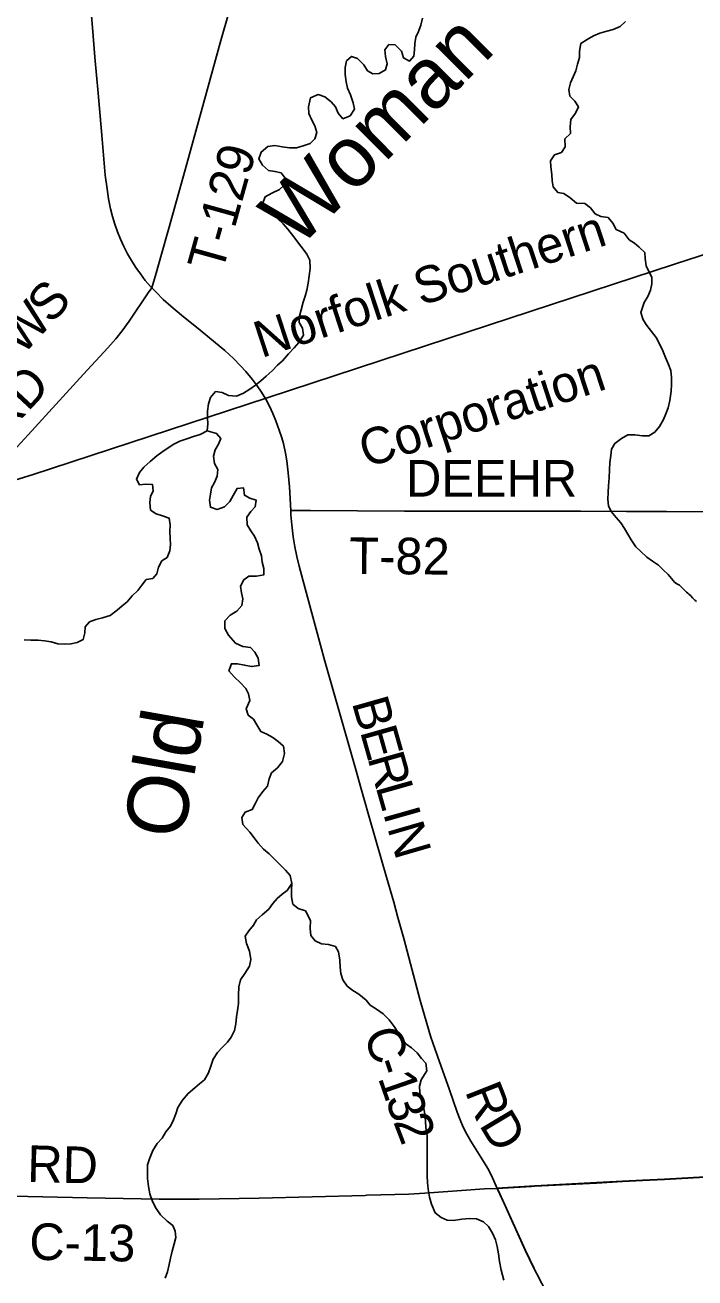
# Model space of a CAD drawing. Extents: x 0 to 34, y 0 to 22.
# Drawn here: x 5.679 to 6.721, y 14.854 to 16.8 of the extents above; entities that cross this region are included whole.
import ezdxf

# ---------------------------------------------------------------- set-up
doc = ezdxf.new("R2010")
doc.units = 0
for name, color, linetype in [('GM_X_Corporation', 7, 'Continuous'), ('GM_X_County_Road', 7, 'Continuous'), ('GM_X_County_Road_Text', 7, 'Continuous'), ('GM_X_Minor_River', 7, 'Continuous'), ('GM_X_Minor_River_Text', 7, 'Continuous'), ('GM_X_Rail_Line', 7, 'Continuous'), ('GM_X_Rail_Line_Text', 7, 'Continuous'), ('GM_X_Township_Road', 7, 'Continuous'), ('GM_X_Township_Road_Text', 7, 'Continuous')]:
    doc.layers.add(name, color=color, linetype=linetype)

msp = doc.modelspace()

# ---------------------------------------------------------------- linework, layer by layer
at = {"layer": 'GM_X_Corporation'}
msp.add_lwpolyline([(6.791, 15.0147), (6.6732, 15.0079), (6.6391, 15.0062), (6.6081, 15.0045), (6.5678, 15.0024), (6.4717, 14.9974), (6.4132, 14.994), (6.4174, 14.9849), (6.4571, 14.8976), (6.4704, 14.8695), (6.4789, 14.8529)], dxfattribs=at)
at = {"layer": 'GM_X_County_Road'}
for p, q in [((6.4135, 14.9934), (6.4669, 14.9965)), ((6.425, 14.968), (6.4135, 14.9934))]:
    msp.add_line(p, q, dxfattribs=at)
for points in [[(5.8764, 16.3924), (5.8745, 16.3944), (5.8664, 16.4039), (5.8588, 16.4138), (5.8516, 16.424), (5.8449, 16.4345), (5.8386, 16.4453), (5.8329, 16.4564), (5.8277, 16.4678), (5.823, 16.4793), (5.8188, 16.4911), (5.8152, 16.503), (5.8123, 16.5152), (5.8093, 16.5305), (5.8069, 16.5458), (5.8042, 16.5675), (5.7991, 16.6232), (5.7932, 16.6945), (5.7881, 16.7503), (5.7848, 16.7905), (5.78, 16.8464)], [(5.5248, 15.9929), (5.5342, 16.0022), (5.5619, 16.0317), (5.5916, 16.0636), (5.6144, 16.089), (5.6443, 16.1207), (5.6844, 16.164), (5.7705, 16.2581), (5.8083, 16.2993), (5.8207, 16.3133), (5.8305, 16.3254), (5.8415, 16.3406), (5.871, 16.3844), (5.8764, 16.3924)], [(6.0924, 16.0464), (6.0903, 16.083), (6.0884, 16.1047), (6.0862, 16.1233), (6.0842, 16.1355), (6.081, 16.1506), (6.0786, 16.1595), (6.0747, 16.1712), (6.0694, 16.1858), (6.0646, 16.1972), (6.0593, 16.2084), (6.0535, 16.2194), (6.0471, 16.23), (6.0402, 16.2403), (6.0327, 16.2502), (6.0228, 16.2621), (6.0145, 16.2713), (6.0035, 16.2823), (5.9898, 16.2949), (5.9757, 16.307), (5.9516, 16.3266), (5.9225, 16.35), (5.9058, 16.364), (5.8942, 16.3744), (5.883, 16.3853), (5.8764, 16.3924)], [(6.3236, 15.1901), (6.3103, 15.2285), (6.3039, 15.2494), (6.2938, 15.2853), (6.2683, 15.3814), (6.2591, 15.4143), (6.2525, 15.4383), (6.2411, 15.477), (6.2335, 15.5039), (6.2147, 15.5685), (6.2061, 15.5996), (6.2049, 15.6026), (6.2048, 15.6034), (6.2021, 15.614), (6.1932, 15.6456), (6.1692, 15.7288), (6.1456, 15.8126), (6.1185, 15.9116), (6.1056, 15.9597), (6.102, 15.9748), (6.099, 15.9901), (6.0964, 16.0055), (6.0941, 16.024), (6.0928, 16.0395), (6.0924, 16.0464)], [(6.4135, 14.9934), (6.4044, 15.0135), (6.3986, 15.0244), (6.3907, 15.0377), (6.3724, 15.0667), (6.3662, 15.0775), (6.3606, 15.0887), (6.3556, 15.1001), (6.3511, 15.1118), (6.339, 15.1464), (6.3256, 15.1845), (6.3236, 15.1901)], [(6.4669, 14.9965), (6.4719, 14.9968), (6.568, 15.0018), (6.6083, 15.004), (6.6393, 15.0057), (6.6734, 15.0073), (6.7912, 15.0141), (6.8284, 15.0168), (6.8438, 15.0183), (6.8684, 15.0214), (6.9174, 15.0289), (6.9602, 15.0362), (6.9969, 15.0426), (7.0239, 15.0475)], [(6.2079, 14.9826), (6.2109, 14.9827), (6.2761, 14.9846), (6.3009, 14.9859), (6.3938, 14.9926), (6.4135, 14.9934)], [(5.6189, 14.9816), (5.6612, 14.9812), (5.7761, 14.9788), (5.8879, 14.9768), (5.95, 14.9768), (6.0432, 14.9781), (6.2079, 14.9826)], [(6.5146, 14.789), (6.5068, 14.8036), (6.5039, 14.8097), (6.5004, 14.8144), (6.4956, 14.823), (6.4897, 14.8334), (6.4791, 14.8523), (6.4706, 14.8689), (6.4573, 14.8971), (6.425, 14.968)]]:
    msp.add_lwpolyline(points, dxfattribs=at)
at = {"layer": 'GM_X_Minor_River'}
for points in [[(6.1224, 16.4224), (6.1223, 16.4353), (6.1177, 16.4448), (6.1119, 16.4523), (6.1046, 16.4614), (6.097, 16.4716), (6.0878, 16.4834), (6.0805, 16.4917), (6.0725, 16.4996), (6.0648, 16.5072), (6.0556, 16.5147), (6.0484, 16.523), (6.0525, 16.5337), (6.0631, 16.5395), (6.0748, 16.5449), (6.082, 16.5518), (6.0838, 16.5624), (6.0773, 16.5707), (6.0678, 16.573), (6.0579, 16.5744), (6.0483, 16.5827), (6.0426, 16.5926), (6.0467, 16.6032), (6.0569, 16.6117), (6.0679, 16.6133), (6.0793, 16.6114), (6.0903, 16.6096), (6.1013, 16.6097), (6.1116, 16.6128), (6.1226, 16.6163), (6.1301, 16.6239), (6.1331, 16.6338), (6.13, 16.6441), (6.1253, 16.6528), (6.1207, 16.663), (6.1203, 16.6733), (6.1232, 16.6874), (6.135, 16.6924), (6.1452, 16.689), (6.1552, 16.6811), (6.1621, 16.6736), (6.1663, 16.6637), (6.1736, 16.655), (6.1846, 16.6592), (6.1917, 16.6699), (6.1897, 16.6798), (6.1851, 16.6919), (6.1809, 16.7022), (6.1785, 16.7121), (6.1769, 16.7235), (6.1772, 16.7345), (6.179, 16.7448), (6.187, 16.7516), (6.1961, 16.7487), (6.2061, 16.7388), (6.2118, 16.7294), (6.2202, 16.7249), (6.2297, 16.7253), (6.2395, 16.7307), (6.2425, 16.7402), (6.2398, 16.7516), (6.2386, 16.7619), (6.245, 16.7703), (6.2549, 16.7696), (6.2644, 16.7597), (6.2679, 16.7495), (6.2771, 16.7446), (6.2838, 16.7519), (6.2849, 16.7618), (6.2856, 16.7717), (6.2871, 16.7816), (6.2908, 16.7903), (6.2945, 16.8002), (6.2971, 16.8113)], [(6.6129, 16.806), (6.6046, 16.7984), (6.5939, 16.7934), (6.5837, 16.7907), (6.5731, 16.7876), (6.5632, 16.7837), (6.553, 16.7779), (6.5436, 16.7718), (6.5414, 16.76), (6.5414, 16.7501), (6.5381, 16.7398), (6.5355, 16.7291), (6.5314, 16.72), (6.5273, 16.7108), (6.5247, 16.7002), (6.5263, 16.6899), (6.5339, 16.6824), (6.5397, 16.6733), (6.5352, 16.6637), (6.528, 16.6538), (6.527, 16.6424), (6.5271, 16.6321), (6.5184, 16.6237), (6.5192, 16.6112), (6.5132, 16.6024), (6.5026, 16.5989), (6.4962, 16.5897), (6.4966, 16.5802), (6.4982, 16.5681), (6.4987, 16.5586), (6.5003, 16.5491), (6.5076, 16.5404), (6.5171, 16.5389), (6.527, 16.5321), (6.5365, 16.5238), (6.5498, 16.5232), (6.5583, 16.5164), (6.5655, 16.5073), (6.5747, 16.5032), (6.5857, 16.5013), (6.593, 16.4926), (6.5984, 16.4828), (6.6106, 16.4772), (6.6186, 16.4669), (6.6266, 16.4617), (6.6343, 16.4553), (6.6427, 16.4473), (6.6435, 16.4378), (6.6451, 16.4264), (6.649, 16.4177), (6.6536, 16.4086), (6.6537, 16.3987), (6.6518, 16.3888), (6.6477, 16.3789), (6.6421, 16.3694), (6.6369, 16.3538), (6.6404, 16.3428), (6.6461, 16.334), (6.6534, 16.3246), (6.6607, 16.3151), (6.6657, 16.3053), (6.6707, 16.2943), (6.675, 16.284), (6.6796, 16.2734), (6.6831, 16.2639), (6.6843, 16.2529), (6.6844, 16.2423), (6.6837, 16.232), (6.6819, 16.2172), (6.6793, 16.2061), (6.6756, 16.1966), (6.6718, 16.1875), (6.6655, 16.1768), (6.6583, 16.168), (6.6492, 16.1622), (6.639, 16.1625), (6.6275, 16.164), (6.6162, 16.1639), (6.6067, 16.1581), (6.5965, 16.1505), (6.5912, 16.1417)], [(5.6781, 15.8455), (5.6883, 15.8448), (5.6997, 15.8448), (5.7096, 15.8441), (5.7199, 15.8423), (5.7302, 15.8393), (5.7408, 15.8386), (5.7507, 15.8391), (5.7602, 15.8414), (5.7696, 15.846), (5.7726, 15.8563), (5.7729, 15.8658), (5.7797, 15.8735), (5.7892, 15.8773), (5.7998, 15.8797), (5.8119, 15.8832), (5.8225, 15.8916), (5.8304, 15.8981), (5.838, 15.9046), (5.8459, 15.9138), (5.8546, 15.9222), (5.861, 15.9306), (5.8678, 15.9394), (5.878, 15.9406), (5.8844, 15.9479), (5.887, 15.9585), (5.8923, 15.9681), (5.9006, 15.9735), (5.9047, 15.9838), (5.9054, 15.9936), (5.9049, 16.0031), (5.9045, 16.0138), (5.9048, 16.0241), (5.9036, 16.0343), (5.8933, 16.0381), (5.8834, 16.041), (5.8746, 16.0471), (5.8734, 16.0588), (5.8745, 16.0684), (5.8786, 16.0771), (5.8778, 16.0866), (5.8671, 16.0873), (5.8572, 16.0865), (5.8526, 16.0952), (5.8575, 16.1055), (5.8643, 16.1139), (5.8741, 16.1227), (5.8843, 16.1311), (5.8922, 16.1369), (5.9002, 16.1427), (5.9108, 16.1492), (5.9198, 16.1542), (5.9308, 16.1577), (5.9414, 16.1615), (5.9517, 16.1646), (5.9623, 16.17), (5.9637, 16.1811), (5.9629, 16.1906), (5.9632, 16.2008), (5.9647, 16.2123), (5.9676, 16.2218), (5.9755, 16.2313), (5.9858, 16.2299), (5.9957, 16.225), (6.0083, 16.2239), (6.0189, 16.2286), (6.0291, 16.2347), (6.0378, 16.2409), (6.0457, 16.2477), (6.054, 16.255), (6.0635, 16.2634), (6.0721, 16.2722), (6.0797, 16.2791), (6.0891, 16.2895), (6.0978, 16.299), (6.1049, 16.3074), (6.1121, 16.3185), (6.1105, 16.3295), (6.1055, 16.3386), (6.1058, 16.3481), (6.1088, 16.358), (6.1117, 16.3702), (6.1147, 16.3794), (6.1173, 16.3885), (6.1195, 16.3995), (6.1209, 16.411), (6.1224, 16.4224)], [(5.9623, 16.1704), (5.9771, 16.1659), (5.9836, 16.158), (5.9799, 16.1492), (5.975, 16.1408), (5.9724, 16.1309), (5.974, 16.1195), (5.979, 16.1101), (5.978, 16.0998), (5.9739, 16.0899), (5.9694, 16.0815), (5.9675, 16.072), (5.9664, 16.0625), (5.9677, 16.0514), (5.9779, 16.0481), (5.9893, 16.0523), (5.998, 16.0604), (6.0029, 16.0699), (6.0089, 16.0806), (6.0191, 16.0814), (6.0203, 16.07), (6.0287, 16.0655), (6.0386, 16.0625), (6.0372, 16.0523), (6.0304, 16.0446), (6.0244, 16.0362), (6.0248, 16.0244), (6.0302, 16.0146), (6.036, 16.0066), (6.0406, 15.9964), (6.0433, 15.9862), (6.0468, 15.9759), (6.048, 15.966), (6.0504, 15.9565), (6.0504, 15.9463), (6.0391, 15.9443), (6.0273, 15.9446), (6.0197, 15.9389), (6.0141, 15.9289), (6.0157, 15.9187), (6.018, 15.9092), (6.0162, 15.8989), (6.0087, 15.8901), (5.9985, 15.884), (5.9902, 15.8748), (5.9899, 15.863), (5.9956, 15.8528), (6.0067, 15.8403), (6.0182, 15.8354), (6.03, 15.8336), (6.0368, 15.8264), (6.0418, 15.817), (6.0431, 15.8056), (6.0313, 15.804), (6.0206, 15.8062), (6.0096, 15.808), (6.0001, 15.8083), (5.996, 15.7973), (6.0044, 15.7878), (6.0144, 15.7788), (6.0224, 15.7701), (6.0267, 15.7614), (6.029, 15.7511), (6.023, 15.7381), (6.0265, 15.7287), (6.0345, 15.7222), (6.0399, 15.7135), (6.0457, 15.7033), (6.0552, 15.6988), (6.0647, 15.6939), (6.0731, 15.6875), (6.0812, 15.6803), (6.0828, 15.6689), (6.0794, 15.6567), (6.0719, 15.6468), (6.0625, 15.6388), (6.0587, 15.6296), (6.0561, 15.6182), (6.049, 15.6102), (6.0418, 15.6002), (6.0373, 15.5907), (6.0325, 15.5819), (6.0215, 15.5777), (6.0162, 15.5697), (6.0182, 15.5587), (6.0289, 15.5466), (6.0358, 15.5379), (6.0416, 15.5299), (6.05, 15.5205), (6.0591, 15.5129), (6.0676, 15.5042), (6.0756, 15.4963), (6.0844, 15.4876), (6.0913, 15.4793), (6.094, 15.4671), (6.0937, 15.4565), (6.0938, 15.4462), (6.0958, 15.4352), (6.1038, 15.4284), (6.1152, 15.4247), (6.1229, 15.4095)], [(6.5912, 16.1417), (6.5898, 16.1318), (6.5883, 16.1208), (6.5877, 16.1094), (6.5874, 16.0972), (6.5863, 16.0846), (6.586, 16.0751), (6.5853, 16.0633), (6.5865, 16.0538), (6.5908, 16.0447), (6.5984, 16.0353), (6.6057, 16.027), (6.6111, 16.0183), (6.6165, 16.0099), (6.6215, 16.0008), (6.6291, 15.9899), (6.636, 15.9831), (6.646, 15.974), (6.6547, 15.9676), (6.6639, 15.9616), (6.6712, 15.954), (6.6792, 15.9468), (6.6894, 15.9344)], [(6.6894, 15.9344), (6.6935, 15.9321), (6.6966, 15.9303), (6.6985, 15.9291), (6.7004, 15.9269), (6.7023, 15.9246), (6.705, 15.9224), (6.7077, 15.9197), (6.7096, 15.9178), (6.7115, 15.9163), (6.7142, 15.9137), (6.7169, 15.9107), (6.7188, 15.9088), (6.7207, 15.9069), (6.723, 15.905)], [(6.094, 15.4671), (6.0869, 15.4564), (6.0793, 15.4507), (6.0714, 15.4438), (6.0646, 15.4358), (6.0582, 15.427), (6.048, 15.4182), (6.0393, 15.4105), (6.0345, 15.4021), (6.0273, 15.3933), (6.0217, 15.3853), (6.0236, 15.3739), (6.0283, 15.3618), (6.0303, 15.3489), (6.0281, 15.3386), (6.0209, 15.3271), (6.0141, 15.3172), (6.0116, 15.3065), (6.0113, 15.2936), (6.011, 15.2807), (6.0095, 15.27), (6.0081, 15.2601), (6.007, 15.2491), (6.0052, 15.2388), (5.9999, 15.2285), (5.9939, 15.2205), (5.986, 15.2121), (5.9785, 15.2048), (5.9721, 15.1941), (5.9683, 15.1835), (5.9646, 15.1728), (5.9582, 15.1621), (5.9507, 15.156), (5.9431, 15.1495), (5.9329, 15.141), (5.9243, 15.1307), (5.9171, 15.1193), (5.9138, 15.1094), (5.9104, 15.0998), (5.9055, 15.0899), (5.8984, 15.0815), (5.8924, 15.0716), (5.8848, 15.0632), (5.8781, 15.0521), (5.8728, 15.0395), (5.8699, 15.03), (5.8696, 15.0182), (5.87, 15.0087), (5.8712, 14.9966), (5.8736, 14.9848), (5.8775, 14.973), (5.8833, 14.9624), (5.8898, 14.9526), (5.9005, 14.9428), (5.9089, 14.9356), (5.9128, 14.9269), (5.9136, 14.917), (5.9114, 14.9075), (5.908, 14.8961), (5.9054, 14.885), (5.9032, 14.8751), (5.9007, 14.8637), (5.8973, 14.8538)], [(6.1229, 15.4095), (6.1226, 15.3973), (6.1238, 15.3863), (6.1304, 15.378), (6.1403, 15.3735), (6.1513, 15.3724), (6.162, 15.3691), (6.1666, 15.3607), (6.1689, 15.3482), (6.1694, 15.3372), (6.1702, 15.3273), (6.1733, 15.3174), (6.1802, 15.3076), (6.189, 15.3008), (6.1982, 15.2952), (6.2096, 15.2857), (6.2161, 15.2782), (6.2257, 15.2718), (6.236, 15.2646), (6.2456, 15.2552), (6.2532, 15.245), (6.259, 15.2363), (6.264, 15.2275), (6.2713, 15.2181), (6.2804, 15.2117), (6.2888, 15.2041), (6.2957, 15.195), (6.3023, 15.1879), (6.3039, 15.1761), (6.2952, 15.162), (6.2926, 15.1521), (6.2931, 15.1422), (6.2958, 15.13), (6.2989, 15.1194), (6.3009, 15.1095), (6.3021, 15.0981), (6.3026, 15.0879), (6.3045, 15.0753), (6.3046, 15.0636), (6.3043, 15.0518), (6.3044, 15.0411), (6.3045, 15.0312), (6.3045, 15.0217), (6.3046, 15.0122), (6.305, 15.0027), (6.3063, 14.9925), (6.3082, 14.9796), (6.311, 14.9689), (6.3168, 14.9557), (6.3263, 14.9485), (6.3358, 14.944), (6.3457, 14.9437), (6.3582, 14.9457), (6.3708, 14.9469), (6.3814, 14.9462), (6.3921, 14.9413), (6.4001, 14.9341), (6.4059, 14.9239), (6.4105, 14.9137), (6.4132, 14.9034), (6.4152, 14.8917), (6.4172, 14.8799), (6.4196, 14.8666), (6.4235, 14.851)]]:
    msp.add_lwpolyline(points, dxfattribs=at)
at = {"layer": 'GM_X_Rail_Line'}
msp.add_lwpolyline([(4.7274, 15.7912), (4.9149, 15.8505), (5.235, 15.9568), (5.5432, 16.0566), (5.6906, 16.1019), (6.056, 16.2214), (6.3367, 16.3138), (6.6888, 16.4288), (7.0003, 16.5302), (7.5012, 16.6931), (7.6844, 16.7528), (7.8339, 16.8018), (7.9505, 16.8406), (8.0234, 16.8694), (8.0878, 16.9029), (8.1469, 16.9344), (8.2358, 16.9935), (8.3923, 17.1058), (8.5744, 17.2368), (8.7463, 17.3593), (8.8719, 17.4493), (8.9, 17.4694)], dxfattribs=at)
at = {"layer": 'GM_X_Township_Road'}
for points in [[(5.8764, 16.3924), (5.883, 16.4149), (5.8914, 16.4444), (5.9026, 16.4831), (5.9308, 16.5849), (5.9409, 16.6208), (5.9574, 16.6807), (5.9756, 16.7465), (5.9836, 16.7766), (5.9966, 16.8213), (6.0033, 16.8454)], [(6.0924, 16.0464), (6.1013, 16.0464), (6.123, 16.0466), (6.2692, 16.0456), (6.3407, 16.0453), (6.462, 16.0452), (6.5428, 16.0454), (6.6143, 16.0446), (6.6764, 16.0447), (6.8475, 16.0444), (6.9967, 16.0437), (7.0067, 16.0436)]]:
    msp.add_lwpolyline(points, dxfattribs=at)

# ---------------------------------------------------------------- texts
at = {"layer": 'GM_X_County_Road_Text'}
for s, height, rotation, p in [('S', 0.0568, 47.8549, (5.72, 16.3344)), ('W', 0.0568, 47.4644, (5.6752, 16.2856)), ('RD', 0.05682, 47.0941, (5.6464, 16.1586)), ('B', 0.0568, 285.8119, (6.1871, 15.7483)), ('E', 0.0568, 285.8124, (6.1998, 15.7034)), ('R', 0.0568, 285.8138, (6.2114, 15.6625)), ('L', 0.0568, 285.8124, (6.2241, 15.6176)), ('I', 0.0568, 285.8136, (6.2357, 15.5767)), ('N', 0.0568, 286.1353, (6.2422, 15.5539)), ('C', 0.0568, 286.3807, (6.2061, 15.2352)), ('-', 0.0568, 288.6139, (6.2199, 15.1881)), ('1', 0.0568, 289.1245, (6.2276, 15.1654)), ('3', 0.0568, 289.2934, (6.2391, 15.1322)), ('R', 0.0568, 291.5579, (6.3628, 15.1446)), ('2', 0.0568, 291.0824, (6.2513, 15.0973)), ('D', 0.0568, 300.8881, (6.3844, 15.0923)), ('RD', 0.05682, 358.5245, (5.6823, 15.0037)), ('C-13', 0.05682, 358.974, (5.6857, 14.8827))]:
    msp.add_text(s, height=height, rotation=rotation, dxfattribs=at).set_placement(p)
at = {"layer": 'GM_X_Minor_River_Text'}
for s, rotation, p in [('Woman', 45.0013, (6.1039, 16.4513)), ('Old', 80.0004, (5.9246, 15.5327))]:
    msp.add_text(s, height=0.09475, rotation=rotation, dxfattribs=at).set_placement(p)
at = {"layer": 'GM_X_Rail_Line_Text'}
for s, rotation, p in [('Norfolk Southern', 18.1333, (6.0468, 16.2829)), ('Corporation', 18.1991, (6.2101, 16.1122))]:
    msp.add_text(s, height=0.056629, rotation=rotation, dxfattribs=at).set_placement(p)
at = {"layer": 'GM_X_Township_Road_Text'}
for s, rotation, p in [('T-129', 74.4031, (5.9859, 16.4141)), ('DEEHR', 0, (6.2717, 16.068)), ('T-82', 359.6438, (6.1833, 15.9478))]:
    msp.add_text(s, height=0.05682, rotation=rotation, dxfattribs=at).set_placement(p)

doc.saveas('drawing.dxf')
